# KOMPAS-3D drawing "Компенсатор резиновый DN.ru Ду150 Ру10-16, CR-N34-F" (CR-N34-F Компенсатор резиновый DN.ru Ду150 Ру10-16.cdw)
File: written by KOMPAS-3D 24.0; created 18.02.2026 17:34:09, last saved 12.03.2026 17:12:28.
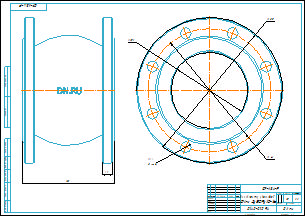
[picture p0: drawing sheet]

Document properties: Типовые: Типовые; Автор: DN.RU; Форматы листов документа: A2; Полное имя файла: CR-N34-F Компенсатор резиновый DN.ru Ду150 Ру10-16.m3d; Масса: 15; Наименование: Компенсатор резиновый DN.ru Ду150 Ру10-16; Количество листов документа: 1; Комментарий: D140-02094; Примечание: D140-02094

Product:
- Body: Твердое тело2  | qty 1
    Масса: 29.199535
- Part/product: Компенсатор резиновый DN.ru Ду150 Ру10-16  | designation CR-N34-F
    Масса: 15
    Раздел спецификации: Прочие изделия
    Форматы листов документа: A2
    Комментарий: D140-02094
    Примечание: D140-02094
    additional columns: Типовые

Views: Вид 1, Спереди, Проекционный вид 2
Referenced files in E:\Работа\Зайцев\CR-N34-F Компенсатор резиновый DN.ru ДУ25-300 Ру10-16\DN150_PN10-16\: CR-N34-F Компенсатор резиновый DN.ru Ду150 Ру10-16.m3d
Referenced files in E:\Работа\Зайцев\Для компаса\: чертеж DN.ru А3.cdt
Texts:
  CR-N34-F
  чертеж DN.ru А3.cdt
  Компенсатор резиновый
  DN.ru Ду150 Ру10-16
  Твердое тело2
  Компенсатор резиновый DN.ru Ду150 Ру10-16
  CR-N34-F Компенсатор резиновый DN.ru Ду150 Ру10-16
Dimensions and other numbers on the sheet: 0; 3; 2; 4; 180; 20; 285; 240; 150; 22; 8 отв.; 1:1; 1; 15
